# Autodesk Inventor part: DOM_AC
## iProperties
Created: 2006-08
Part Number: DOM_AC
Document SubType Name: Blech
Designer: WINDGES
Material: Steel
Author: WINDGES
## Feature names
1. Extrusion1
2. Extrusion2
3. Extrusion3
